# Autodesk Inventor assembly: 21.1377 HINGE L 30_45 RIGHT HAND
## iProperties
Created: 2007-01
Part Number: 21.1377 HINGE L 30_45 RIGHT HAND
Document SubType Name: Assembly
Designer: Andy Moles
Author: Andy Moles
